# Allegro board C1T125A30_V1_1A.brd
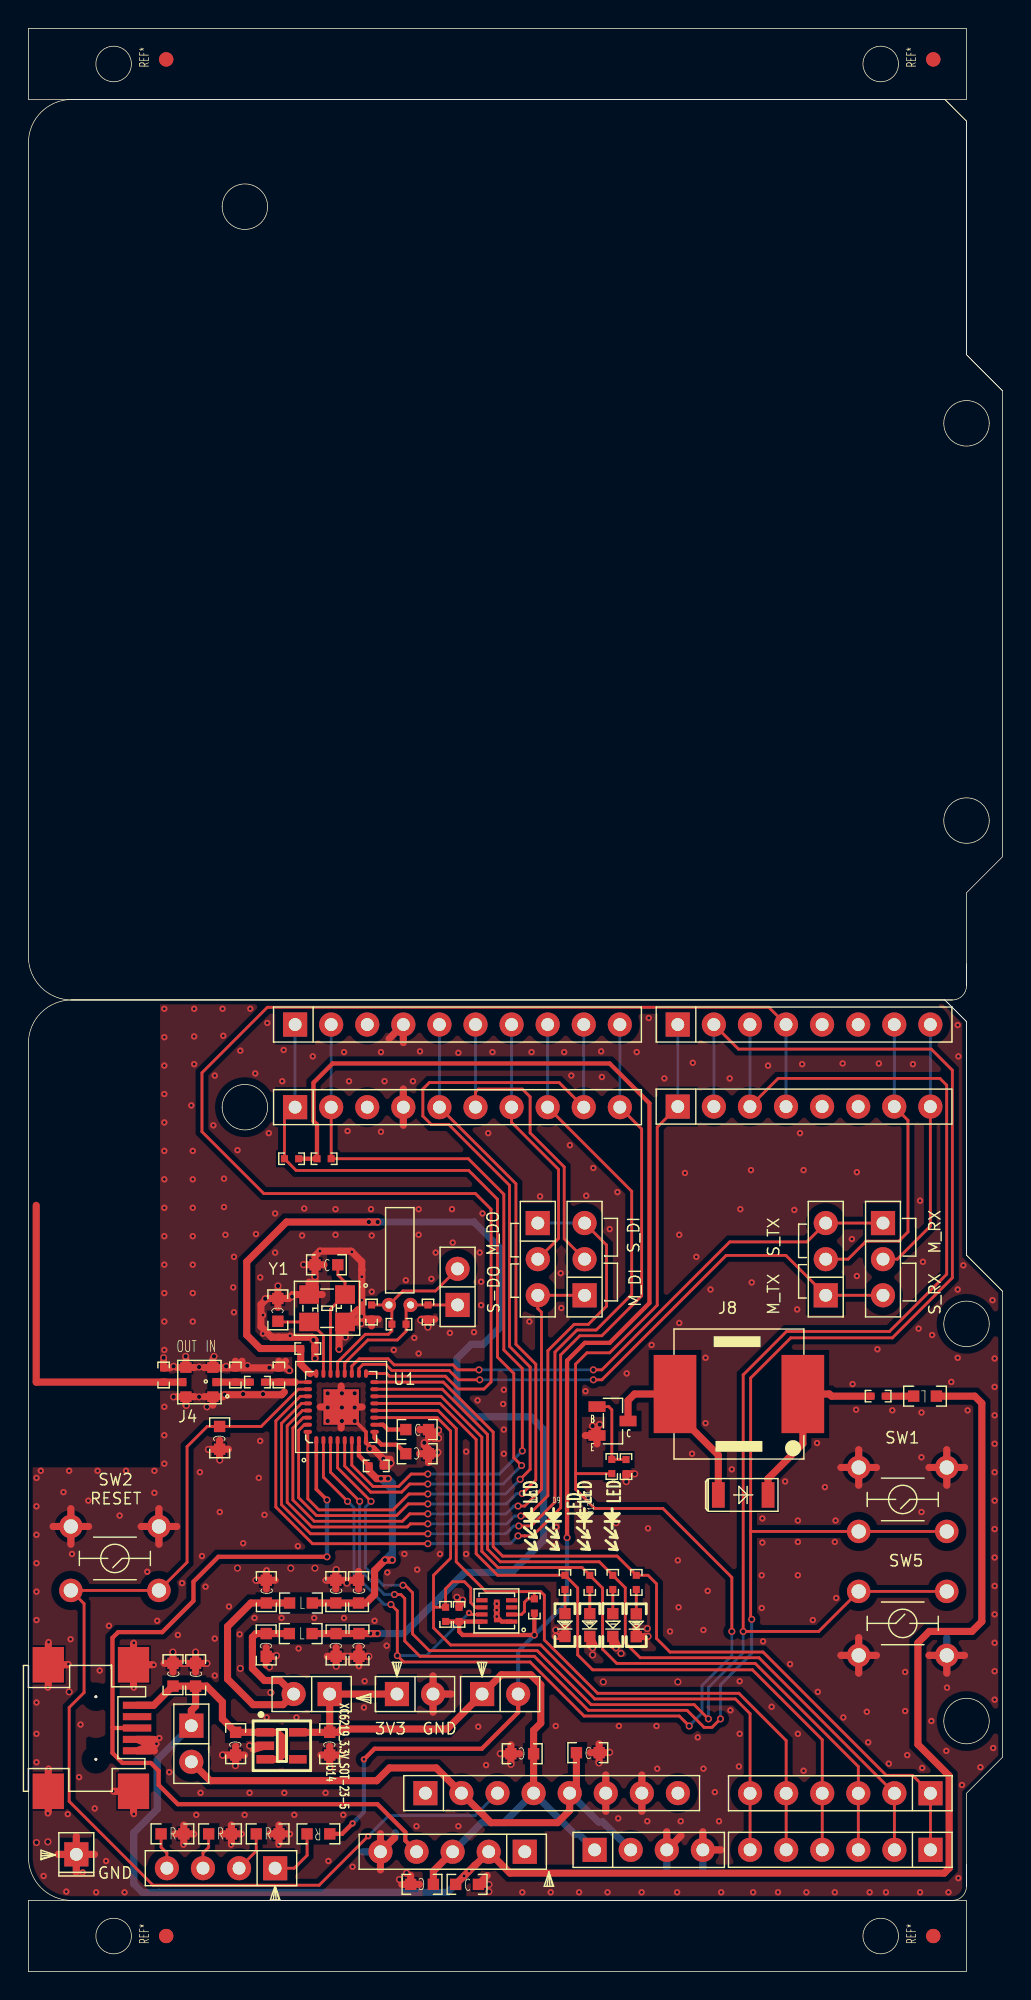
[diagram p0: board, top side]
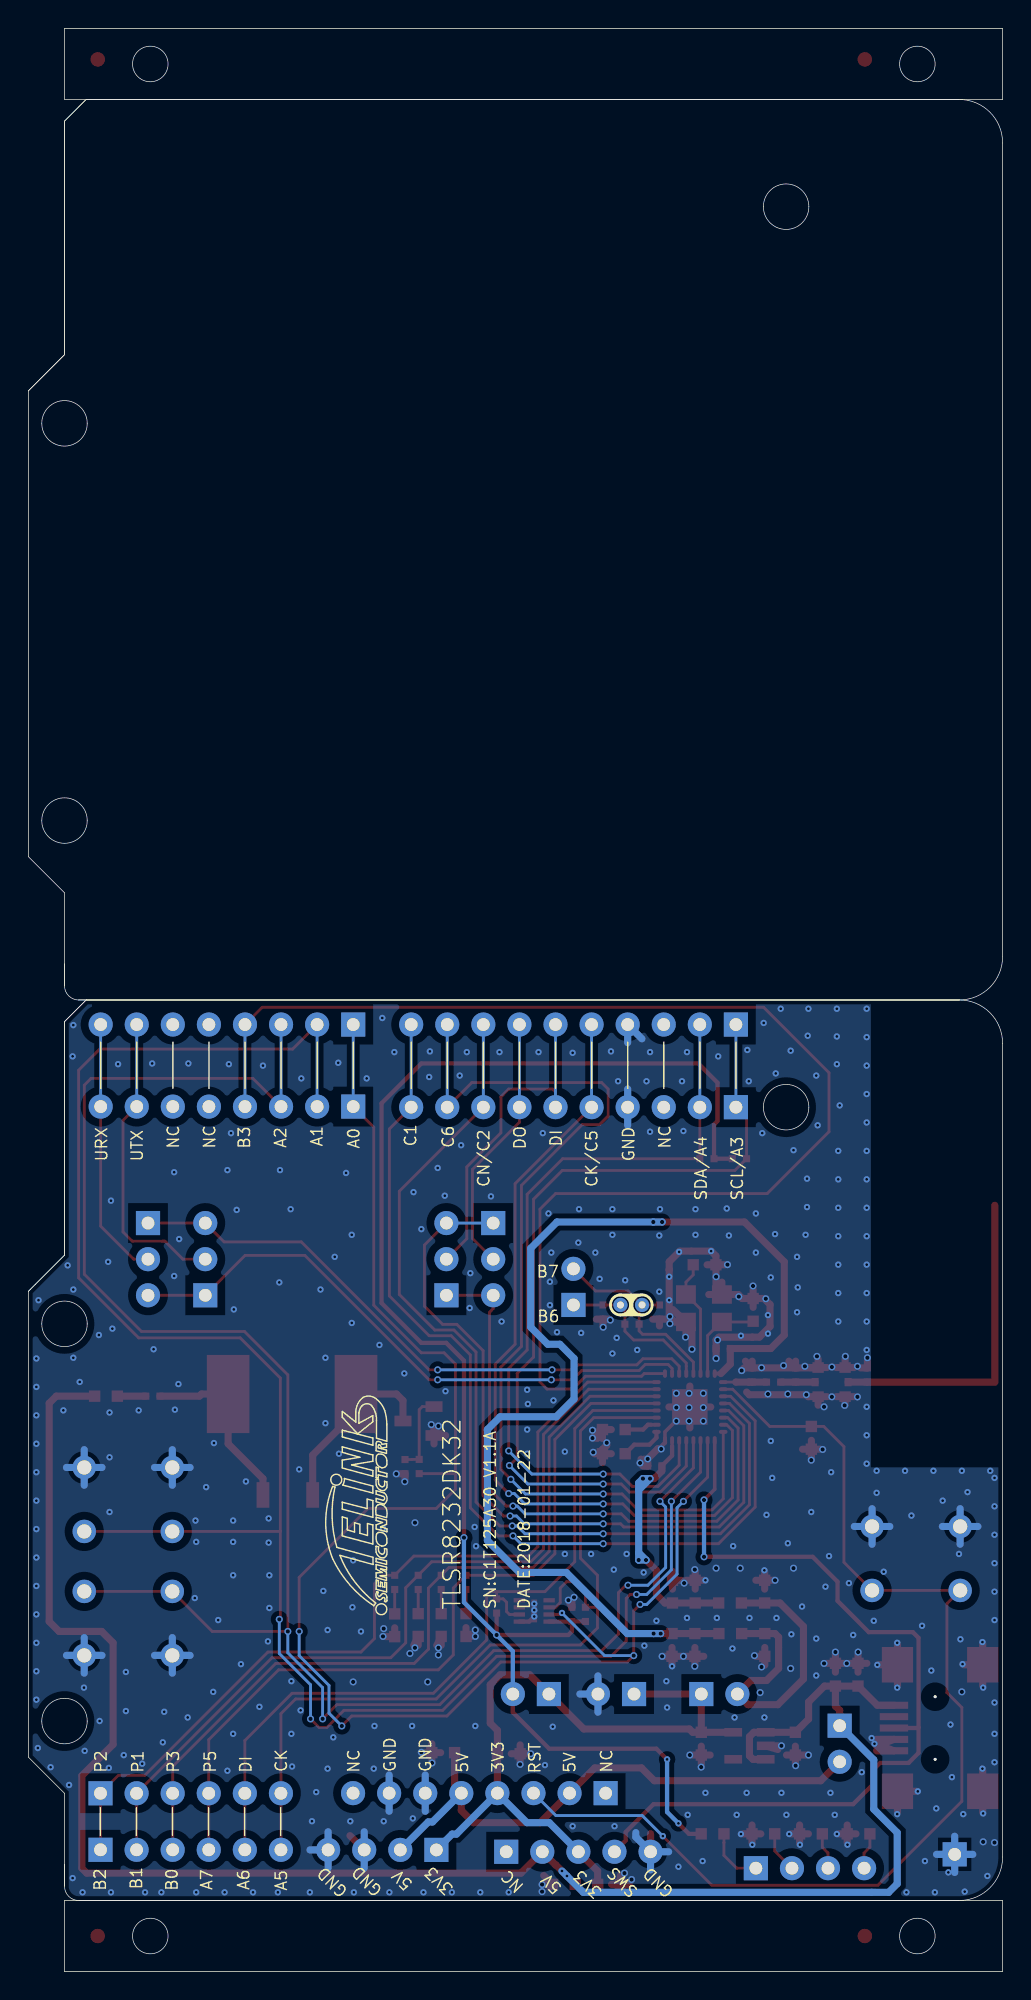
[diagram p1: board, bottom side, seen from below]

Outline 68.58 x 136.68 mm; copper layers: TOP, BOTTOM. Coordinates in mm from the lower left corner of the outline.
Outline path: circle c6,134.18 r1.25 ; circle c6,2.5 r1.25 ; circle c60,134.18 r1.25 ; circle c60,2.5 r1.25 ; 3.05,131.68 arc(0.89,130.79) 0,128.63 0,71.39 arc(0.89,69.23) 3.05,68.34 ; 3.05,131.68 64.52,131.68 ; 3.05,131.68 64.52,131.68 ; 3.05,68.34 arc(0.89,67.45) 0,65.29 0,8.05 arc(0.89,5.89) 3.05,5 ; 3.05,68.34 64.52,68.34 ; 3.05,68.34 65.04,68.34 ; 3.05,68.34 64.52,68.34 ; 3.05,68.34 65.04,68.34 ; 64.52,131.68 66.04,130.16 ; 64.52,131.68 66.04,130.16 ; 64.52,68.34 66.04,66.82 ; 64.52,68.34 66.04,66.82 ; 65.04,68.34 arc(65.75,68.63) 66.04,69.34 ; 3.05,5 65.04,5 ; 3.05,5 65.04,5 ; 65.04,5 arc(65.75,5.29) 66.04,6 ; 66.04,130.16 66.04,113.73 ; 66.04,130.16 66.04,113.73 ; 66.04,66.82 66.04,50.39 ; 66.04,66.82 66.04,50.39 ; 66.04,113.73 68.58,111.19 ; 66.04,113.73 68.58,111.19 ; 68.58,111.19 68.58,78.42 66.04,75.88 66.04,70.88 ; 66.04,70.88 66.04,69.34 ; 66.04,70.88 66.04,69.34 ; 66.04,50.39 68.58,47.85 ; 66.04,50.39 68.58,47.85 ; 68.58,47.85 68.58,15.08 66.04,12.54 66.04,7.54 ; 66.04,7.54 66.04,6 ; 66.04,7.54 66.04,6 ; 0,136.68 0,131.68 66.04,131.68 66.04,136.68 0,136.68 ; 0,5 66.04,5 66.04,0 0,0 0,5 ; 13.64,124.14 arc(15.24,125.74) 16.84,124.14 arc(15.24,122.54) 13.64,124.14 ; 13.64,60.8 arc(15.24,62.4) 16.84,60.8 arc(15.24,59.2) 13.64,60.8 ; 64.44,108.9 arc(66.04,110.5) 67.64,108.9 arc(66.04,107.3) 64.44,108.9 ; 64.44,80.96 arc(66.04,82.56) 67.64,80.96 arc(66.04,79.36) 64.44,80.96 ; 64.44,45.56 arc(66.04,47.16) 67.64,45.56 arc(66.04,43.96) 64.44,45.56 ; 64.44,17.62 arc(66.04,19.22) 67.64,17.62 arc(66.04,16.02) 64.44,17.62

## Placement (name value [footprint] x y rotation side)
C3  1uF  [0603C1]  13.46 37.54 270 top
C6  1uF  [0603C1]  27.37 36.42 180 top
C7  NC/1uF  [0402]  30.32 25.12 90 top
C9  1uF  [0603C1]  27.37 38.12 0 top
C10  NC  [0603C1]  20.98 49.72 0 top
C11  10uF  [0603C1]  34.76 15.32 180 top
C12  10uF  [0603C1]  39.38 15.4 0 top
C13  NC  [0603C1]  17.56 46.54 270 top
C14  1uF  [0603C1]  14.59 16.03 270 top
C15  NC  [0402]  24.16 46.39 90 top
C16  NC  [0402]  28.13 46.39 90 top
C17  1uF  [0603C1]  21.21 16.03 270 top
C18  1uF  [0603C1]  11.77 20.88 90 top
C19  10uF  [0603C1]  10.18 20.88 90 top
C20  1uF  [0603C1]  16.75 26.72 90 top
C21  0.1uF  [0603C1]  21.64 26.72 90 top
C22  1uF  [0603C1]  23.24 26.72 90 top
C23  0.1uF  [0402]  24.48 35.57 0 top
C24  1uF  [0603C1]  16.74 22.97 270 top
C25  0.1uF  [0603C1]  21.66 22.97 270 top
C26  1uF  [0603C1]  23.27 22.97 270 top
C27  0.1uF  [0402]  19.67 43.82 0 top
C33  1.8pF  [0402]  14.57 41.96 90 top
C34  1.8pF  [0402]  17.63 41.96 90 top
C39  NC/10uF  [0603C1]  27.71 6.13 180 top
C43  NC/10uF  [0603C1]  30.88 6.13 0 top
D1  Blue  [0603-LED]  39.52 24.37 270 top
D2  Green  [0603-LED]  37.77 24.37 270 top
D3  White  [0603-LED]  41.14 24.37 270 top
D4  Red  [0603-LED]  42.79 24.36 270 top
D7  NC/1N4148  [SOD80]  50.32 33.52 0 top
J3  HEADER 5  [HDR254F-1X5X850]  24.78 8.43 0 top
J4  MM8130  [MM8130-2600]  12.04 41.46 270 top
J5  VCC  [HDR254F-1X2X850]  11.47 14.75 90 top
J8  NC/Buzzer  [BUZZER]  50.02 40.62 180 top
J10  HEADER 1X2  [HDR254F-1X2X850]  30.21 49.43 270 top
J12  B2S  [HDR254F-1X2X850]  18.67 19.52 0 top
J13  NC  [HDR254F-1X2X850]  34.48 19.52 180 top
J15  USB_MiniABF  [USB-MINI-F5]  7.65 17.13 270 top
J18  Header_Femal  [HDR254F-1X6X850]  50.8 12.54 0 top
J19  Header_Femal  [HDR254F-1X8X850]  45.72 12.55 180 top
J20  Header_Femal  [HDR254F-1X10X850]  41.63 60.8 180 top
J21  Header_Mal  [HDR254F-1X6X850]  50.8 8.56 0 top
J22  Header_Femal  [HDR254F-1X8X850]  63.49 60.84 180 top
J29  Header_Mal  [HDR254F-1X10X850]  41.63 66.61 180 top
J31  Header_Mal  [HDR254F-1X8X850]  63.49 66.61 180 top
J32  Header_Mal  [HDR254F-1X4X850]  47.48 8.56 180 top
J33  UTX Jumper  [HDR254F-1X3X850]  56.13 52.65 270 top
J34  URX Jumper  [HDR254F-1X3X850]  60.16 47.57 90 top
J35  SPI_DO Jumper  [HDR254F-1X3X850]  35.86 47.57 90 top
J36  SPI_DI Jumper  [HDR254F-1X3X850]  39.15 52.65 270 top
J37  HEADER 4  [HDR254F-1X4X850]  9.75 7.27 0 top
J38  NC  [HDR254F-1X2X850]  28.48 19.52 180 top
J39  NC  [HDR254F-1X1X850]  3.37 8.24 90 top
L1  1.5nH  [0402]  9.52 41.96 90 top
L2  BEAD_600  [0603L1]  19.17 23.77 0 top
L3  BEAD_600  [0603L1]  19.19 25.92 0 top
L7  2.2nH  [0402]  16.12 41.46 180 top
L8  BEAD_600  [0603L1]  63.12 40.47 180 top
Q3  NC/8050  [BJT_SOT-23]  41.12 38.72 270 top
R1  NC  [0402]  26.09 45.54 180 top
R4  3.3K  [0402]  39.52 27.37 270 top
R5  750R  [0402]  37.77 27.37 270 top
R6  750R  [0402]  41.14 27.37 270 top
R7  750R  [0402]  42.79 27.37 270 top
R10  NC/1K  [0402]  41.07 35.52 90 top
R11  NC/2R  [0402]  59.82 40.47 0 top
R14  NC/3.3K  [0402]  18.53 57.17 180 top
R15  NC/3.3K  [0402]  20.81 57.17 0 top
R16  NC/2.2K  [0402]  35.62 25.72 90 top
R17  NC/2.2K  [0402]  29.37 25.12 90 top
R25  NC/1M  [0402]  42.07 35.52 270 top
R42  10K  [0603R]  16.84 9.69 0 top
R43  100K  [0603R]  20.42 9.69 180 top
R44  1M  [0603R]  13.49 9.69 0 top
R45  50K  [0603R]  10.14 9.69 0 top
REF*  value*  [unnamed]  9.7 134.5 90 top
REF*#2  value*  [unnamed]  63.7 2.5 90 top
REF*#3  value*  [unnamed]  9.7 2.5 90 top
REF*#4  value*  [unnamed]  63.7 134.5 90 top
SW1  SW4PIN_4.5x4.5  [BUTDIP4P_5P0X3P0]  61.55 33.21 180 top
SW2  SW4PIN_4.5x4.5  [BUTDIP4P_5P0X3P0]  6.09 29.06 180 top
SW5  SW4PIN_4.5x4.5  [BUTDIP4P_5P0X3P0]  61.55 24.49 0 top
U1  TLSR8232F512ET32  [QFN_5X5_32PIN_0P5_2P50X2P50]  22.02 39.71 90 top
U4  CE1132-33M  [SOT-23-5]  17.82 15.88 270 top
U5  NC/MFI  [CP]  32.97 25.37 90 top
Y1  24Mhz  [OSCCC250X320X110]  21.03 46.66 270 top
Y2  NC/32.768Khz-9pf-+/-20ppm  [OSC_2X6]  26.14 50.89 270 top

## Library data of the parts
C3 C6 C9 C14 C17 C18 C22 C26 = C1608X5R1C105M
C7 = C1005X5R1C105K
C10 C13 C15 C16 = C1608_NC
C11 C12 C19 C20 C24 C39 C43 = C1608X5R0J106M
C21 C25 = C1608X5R1H104M
C23 C27 = C1608X5R1H103K
C33 C34 = C1005_NC
D1-D4 = 0603D_Green
D7 = Diode_1N4148
J3 = HEADER 5: User Part Number: pn; Tolerance: RichardLC
J4 = MM8130
J5 J10 = B2S_3: User Part Number: pn; Tolerance: RichardLC
J8 = CONN MOD 8-2_J_0
J12 J13 = B2S_0: User Part Number: pn; Tolerance: RichardLC
J15 = USB_MiniABF_5pin: User Part Number: pn; Tolerance: RichardLC
J18 J21 = HEADER 6: User Part Number: pn; Tolerance: RichardLC
J19 J22 J31 = HEADER 8: User Part Number: pn; Tolerance: RichardLC
J20 J29 = HEADER 10: User Part Number: pn; Tolerance: RichardLC
J32 J37 = HEADER 4: User Part Number: pn; Tolerance: RichardLC
J33-J36 = HEADER 3: User Part Number: pn; Tolerance: RichardLC
J38 = HEADER 2: User Part Number: pn; Tolerance: RichardLC
J39 = HEADER 1: User Part Number: pn; Tolerance: RichardLC
L1 = MLK1005_000R
L2 L3 = MMZ1608Y601C
L7 = MLK1005S2N2ST
L8 = MMZ1005Y601C
Q3 = NPN_C1815
R1 = RS0402_NC
R4-R7 R10 R11 R25 = RS0402K102JT
R14 R15 = RS0402K332JT
R16 R17 = RS0402K222JT
R42-R45 = RS0603K104JT
SW1 SW2 SW5 = SW4PIN_0.5
U1 = TLSR8232F512ET32
U4 = XC6219_0.3V_SOT-23-5
U5 = XC6219_3.3V_SOT-23-5: User Part Number: pn; Tolerance: RichardLC
Y1 = CRYSTAL4/SM_0: Tolerance: RichardLC
Y2 = OSC_2x6_2pin

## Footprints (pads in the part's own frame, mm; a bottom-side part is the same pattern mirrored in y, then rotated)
0402
  rect 0.5x0.5 smd: 1(-0.5,0) 2(0.5,0)
0603-LED
  rect 0.8x0.8 smd: A(-0.8,0) C(0.8,0)
0603C1
  rect 0.8x0.8 smd: 1(-0.8,0) 2(0.8,0)
0603L1
  rect 0.8x0.8 smd: 1(-0.8,0) 2(0.8,0)
0603R
  rect 0.8x0.8 smd: 1(-0.8,0) 2(0.8,0)
BJT_SOT-23
  rect 0.75x1.2 smd: 1(-1.016,-1.092) 2(1.016,-1.092) 3(0,1.092)
BUTDIP4P_5P0X3P0
  round 1.65 hole 1: 1(-3.1,2.25) 2(-3.1,-2.25) 3(3.1,2.25) 4(3.1,-2.25)
BUZZER
  rect 3x5.5 smd: 1(-4.5,0) 2(4.5,0)
CP
  rect 0.3x0.8 smd: 1(-0.75,-1.05) 2(-0.25,-1.05) 3(0.25,-1.05) 4(0.75,-1.05) 5(0.75,1.05) 6(0.25,1.05) 7(-0.25,1.05) 8(-0.75,1.05)
  rect 1.6x0.4 smd: 9(0,0)
HDR254F-1X1X850
  rect 1.7x1.7 hole 0.9: 1(0,0)
HDR254F-1X2X850
  rect 1.7x1.7 hole 0.9: 1(2.54,0)
  round 1.7 hole 0.9: 2(0,0)
HDR254F-1X3X850
  rect 1.7x1.7 hole 0.9: 1(5.08,0)
  round 1.7 hole 0.9: 2(2.54,0) 3(0,0)
HDR254F-1X4X850
  rect 1.7x1.7 hole 0.9: 1(7.62,0)
  round 1.7 hole 0.9: 2(5.08,0) 3(2.54,0) 4(0,0)
HDR254F-1X5X850
  rect 1.7x1.7 hole 0.9: 1(10.16,0)
  round 1.7 hole 0.9: 2(7.62,0) 3(5.08,0) 4(2.54,0) 5(0,0)
HDR254F-1X6X850
  rect 1.7x1.7 hole 0.9: 1(12.7,0)
  round 1.7 hole 0.9: 2(10.16,0) 3(7.62,0) 4(5.08,0) 5(2.54,0) 6(0,0)
HDR254F-1X8X850
  rect 1.7x1.7 hole 0.9: 1(17.78,0)
  round 1.7 hole 0.9: 2(15.24,0) 3(12.7,0) 4(10.16,0) 5(7.62,0) 6(5.08,0) 7(2.54,0) 8(0,0)
HDR254F-1X10X850
  rect 1.7x1.7 hole 0.9: 1(22.86,0)
  round 1.7 hole 0.9: 2(20.32,0) 3(17.78,0) 4(15.24,0) 5(12.7,0) 6(10.16,0) 7(7.62,0) 8(5.08,0) 9(2.54,0) 10(0,0)
MM8130-2600
  rect 0.58x0.5 smd: 1(0,1.16) 2(0,-1.16)
  rect 0.75x0.8 smd: 3(-1.025,0.95) 4(1.025,0.95) 5(-1.025,-0.95) 6(1.025,-0.95)
OSC_2X6
  round 1 hole 0.5: 1(4,0.76) 2(4,-0.76)
OSCCC250X320X110
  rect 1.3x1.4 smd: 1(-0.965,1.265) 2(-0.965,-1.265) 3(0.965,-1.265) 4(0.965,1.265)
QFN_5X5_32PIN_0P5_2P50X2P50
  oval 0.6x0.28 smd: 1(-2.35,1.75) 2(-2.35,1.25) 3(-2.35,0.75) 4(-2.35,0.25) 5(-2.35,-0.25) 6(-2.35,-0.75) 7(-2.35,-1.25) 8(-2.35,-1.75) 17(2.35,-1.75) 18(2.35,-1.25) 19(2.35,-0.75) 20(2.35,-0.25) 21(2.35,0.25) 22(2.35,0.75) 23(2.35,1.25) 24(2.35,1.75)
  oval 0.28x0.6 smd: 9(-1.75,-2.35) 10(-1.25,-2.35) 11(-0.75,-2.35) 12(-0.25,-2.35) 13(0.25,-2.35) 14(0.75,-2.35) 15(1.25,-2.35) 16(1.75,-2.35) 25(1.75,2.35) 26(1.25,2.35) 27(0.75,2.35) 28(0.25,2.35) 29(-0.25,2.35) 30(-0.75,2.35) 31(-1.25,2.35) 32(-1.75,2.35)
  rect 2.5x2.5 smd: 33(0,0)
SOD80
  rect 0.9x1.8 smd: A(-1.75,0) C(1.75,0)
SOT-23-5
  rect 0.6x1.25 smd: 1(-0.95,-1.145) 2(0,-1.145) 3(0.95,-1.145) 4(0.95,1.145) 5(-0.95,1.145)
unnamed
  round 1 smd: 1(0,0) 2(0,0)
USB-MINI-F5
  round 0.2 hole 0.9 unplated: (-2.2,-2.9) (2.2,-2.9)
  rect 0.5x2 smd: 1(-1.6,0) 2(-0.8,0) 3(0,0) 4(0.8,0) 5(1.6,0)
  rect 2.5x2.2 smd: 6(-4.45,-6.25) 7(4.45,-6.25) 8(-4.45,-0.25) 9(4.45,-0.25)

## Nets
3V3: C11.1 C17.1 C39.1 J3.3 J12.1 J13.1 J19.4 J32.1 J38.1 U4.5(VOUT)
5V: C12.1 J5.2 J19.2 J19.5 J32.2
DVDD_IO: C7.1 J13.2 R14.1 R15.1 R16.1 R17.1 R43.1 U5.8(VCC)
GND: C3.2 C6.1 C7.2 C9.2 C10.1 C11.2 C12.2 C13.1 C14.2 C15.1 C16.1 C17.2 C18.2 C19.2 C20.2 C21.2 C22.2 C23.2 C24.2 C25.2 C26.2 C27.2 C33.2 C34.2 C39.2 C43.2 D1.C(CATHODE) D2.C(CATHODE) D3.C(CATHODE) D4.C(CATHODE) J3.5 J4.3 J4.4 J4.5 J4.6 J15.4(ID) J15.5(GND) J15.6(S1) J15.7(S2) J15.8(S3) J15.9(S4) J19.6 J19.7 J20.4 J29.4 J32.3 J32.4 J38.2 J39.1 L1.2 Q3.2(E) R25.2 R42.2 R44.2 R45.2 SW1.2 SW1.4 SW2.2 SW2.4 SW5.2 SW5.4 U1.8(DVSS) U1.33(GND) U4.2(VSS) U5.1(GND#1) U5.9(GND#9) Y1.2 Y1.4
VBUS: C14.1 C18.1 C19.1 C43.1 J3.2 J5.1 J15.1(V_BUS) L8.1 U4.1(VIN) U4.3(CE)
BUZ_5V: L8.2 R11.2
DI: J20.6 J29.6 J36.2
DO: J20.7 J29.7 J35.2
TL_A0: J22.1 J31.1 R10.1 U1.2(P0/P3/A[0]) U5.7(RST)
TL_A1: J22.2 J31.2 SW1.1 SW1.3 U1.3(P3N/UCTS/A[1])
TL_A2: J22.3 J31.3 SW5.1 SW5.3 U1.4(P1N/URTS/A[2])
TL_ANT: C34.1 L7.1 U1.25(ANT)
TL_AVDD: C20.1 C24.1 J12.2 L2.1 L3.1
TL_AVDD3_PIN24: C25.1 C26.1 C27.1 L2.2 U1.24(AVDD3)
TL_B3: J22.4 J31.4 U1.17(P0/MCK/URTS/I2CMSD/B[3])
TL_B6: C16.2 J10.1 R1.1 U1.20(P0N/I2C_MCK/URTS/B[6]) Y2.1
TL_B7: C15.2 J10.2 R1.2 U1.21(P1/I2C_MSD/UCTS/B[7]) Y2.2
TL_C1: J20.10 J29.10 U1.27(P2N/C[1])
TL_C6: J20.9 J29.9 U1.32(P4/C[6])
TL_CK/A5: J18.6 J21.6 R17.2 U1.11(P5/I2C_CK_MCK/A[5]) U5.6(SCL)
TL_CK/C5: J20.5 J29.5 U1.31(CK/I2C_MCK/MCK/URX/C[5])
TL_CN/C2: J20.8 J29.8 U1.28(CN/P0N/MCN/UCTS/C[2])
TL_DI/A6: J18.5 J21.5 R16.2 U1.12(P4N/I2C_SD_MSD/A[6]) U5.2(SDA)
TL_DI/C4: J35.3 J36.1 U1.30(DI/I2C_MSD/MDI/UTX/C[4])
TL_DO/C3: J35.1 J36.3 U1.29(DO/P5N/MDO/URTS/C[3])
TL_DVDD3: C21.1 C22.1 C23.1 L3.2 U1.7(DVDD3)
TL_DVDD3F: C9.1 U1.10(DVDD3_F)
TL_I2CCK/A3: J20.1 J29.1 R14.2 U1.5(P4/UTX/I2C_MCK/DI/A[3])
TL_I2CDI/A4: J20.2 J29.2 R15.2 U1.6(P2/URX/I2C_MSD/CK/A[4])
TL_P1/B1: J18.2 J21.2 R6.1 U1.15(P1/MDO/B[1])
TL_P2/B2: J18.1 J21.1 R7.1 U1.16(P2/MDI/UCTS/I2CMCK/B[2])
TL_P3/B0: J18.3 J21.3 R4.1 U1.14(P3/MCN/B[0])
TL_P5/A7: J18.4 J21.4 R5.1 U1.13(P5/A[7])
TL_RST: C3.1 J19.3 SW2.1 SW2.3 U1.26(RESETB)
TL_SWS: J3.4 J15.3(D+) U1.1(SWS/P3/C[7])
TL_URX/B5: J33.3 J34.1 U1.19(P4/URX/B[5])
TL_UTX/B4: J33.1 J34.3 U1.18(P1N/UTX/B[4])
TL_XC1: C13.2 U1.23(XC1) Y1.3
TL_XC2: C10.2 U1.22(XC2) Y1.1
URX: J22.8 J31.8 J34.2
UTX: J22.7 J31.7 J33.2
N19433324: Q3.1(B) R10.2 R25.1
N19433336: D7.A J8.2 Q3.3(C)
N19433338: D7.C J8.1 R11.1
N19452982: C6.2 U1.9(VDDDEC)
N19453491: C33.1 J4.1 L7.2
N19453517: J4.2 L1.1
N19478691: J37.2 R42.1
N19478703: J37.3 R44.1
N19478721: J37.4 R45.1
N19478794: J37.1 R43.2
N194550181: D4.A(ANODE) R7.2
N194550261: D2.A(ANODE) R5.2
N194550340: D1.A(ANODE) R4.2
N194550500: D3.A(ANODE) R6.2

Pads without a net: J3 1; J15 2; J19 1 8; J20 3; J22 5 6; J29 3; J31 5 6; REF* 1 2; REF*#2 1 2; REF*#3 1 2; REF*#4 1 2; U4 4; U5 3 4 5

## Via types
v1: diameter 0.5, hole 0.3, TOP to BOTTOM, 142 vias
v2: diameter 0.45, hole 0.2, TOP to BOTTOM, 358 vias

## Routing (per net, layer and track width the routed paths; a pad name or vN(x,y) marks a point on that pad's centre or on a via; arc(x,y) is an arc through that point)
3V3: length 50.5
  TOP w0.5: C17.1 21.82,16.83 22.05,17.06 29.48,17.06 J13.1 33.29,20.87 35.37,20.87 36.07,20.17 36.07,17.47 35.56,16.97 C11.1 J19.4 ; C17.1 U4.5 ; C17.1 J12.1 J38.1 ; C39.1 28.51,7.07 J3.3
  BOTTOM w0.5: J3.3 31.91,10.47 33.49,10.47 J19.4 38.45,9.67 38.75,9.67 J32.1
5V: length 39.7
  TOP w0.5: J5.2 12.8,13.42 24.52,13.42 25.42,14.32 28.71,14.32 J19.2 32.56,10.47 37.25,10.47 38.1,11.33 J19.5 38.58,13.03 C12.1
  BOTTOM w0.5: J19.5 40.13,10.52 40.43,10.52 J32.2
DVDD_IO: length 109
  TOP w0.3: U5.8 30.33,24.62 C7.1 ; v2(22.82,10.42) 22.08,9.69 R43.1 ; C7.1 30.32,23.92 30.57,23.67 v1(35.62,23.67) R16.1 ; C7.1 R17.1 ; R14.1 R15.1 20.31,59.58 20.07,59.82 20.07,62.52 21.42,63.87 40.92,63.87 43.72,61.07 43.72,47.02 40.92,44.22 39.17,44.22 37.92,42.97 v1(37.92,30.52) ; v2(23.62,14.92) 24.37,15.67 31.92,15.67 34.48,18.23 J13.2
  BOTTOM w0.3: J13.2 34.48,22.53 v1(35.62,23.67) 37.92,25.97 v1(37.92,30.52) ; v2(23.62,14.92) 23.62,11.22 v2(22.82,10.42)
GND: length 265.1
  TOP w0.25: U1.33 23.77,37.96 U1.8
  TOP w0.3: U5.1 33.33,24.62 32.97,24.97 U5.9 ; 24.19,36.77 23.77,37.2 U1.8
  TOP w0.5: J15.8 7.4,23.05 ; J15.8 8.72,21.58 ; J15.8 7.4,20.11 ; C13.1 17.56,47.96 ; C13.1 18.33,47.34 18.61,47.62 Y1.2 ; C13.1 17.56,46.72 ; C13.1 16.79,47.34 16.37,46.92 16.37,45.37 17.12,44.62 17.62,44.62 ; 11.09,39.84 J4.6 ; J4.6 11.71,40.44 ; J4.6 10.46,40.44 ; U1.33 23.49,39.71 ; U1.33 22.02,38.24 ; U1.33 20.55,39.71 ; U1.33 22.02,41.18 ; C15.1 24.63,45.89 ; C15.1 23.68,45.89 ; C15.1 24.16,45.42 ; 32.3,6.75 C43.2 32.3,6.13 ; SW5.2 58.45,23.49 ; SW5.2 57.2,22.24 ; SW5.2 59.7,22.24 ; SW5.2 58.45,20.99 ; 9.99,42.46 L1.2 9.52,42.93 ; C17.2 21.83,15.23 ; C17.2 21.21,14.61 ; C17.2 20.59,15.23 ; C17.2 21.21,15.85 ; C12.2 40.8,15.4 ; C12.2 40.18,16.02 ; C12.2 40.18,14.78 ; C12.2 39.56,15.4 ; 28.13,45.42 C16.1 ; C16.1 27.66,45.89 ; C16.1 28.6,45.89 ; 41.14,22.95 D3.C 41.45,22.95 ; Y1.2 20.18,48.04 C10.1 ; Y1.2 19.76,48.49 ; Y1.2 20.68,47.62 ; C34.2 18.1,42.93 ; C34.2 C33.2 ; C34.2 18.18,42.46 v1(18.37,42.27) ; C34.2 17.63,42.93 ; C23.2 25.22,36.04 ; C23.2 25.46,36.04 ; C23.2 v1(24.98,36.06) 24.27,36.77 24.19,36.77 ; C23.2 25.32,35.57 v1(25.52,35.77) ; C10.1 20.8,49.72 ; C10.1 19.56,49.72 ; C10.1 20.18,50.34 v2(20.52,50.67) 22.72,50.67 v2(22.77,50.62) 23.47,49.92 23.47,49.37 ; C20.2 16.75,28.15 ; C20.2 16.13,27.52 ; C20.2 16.75,26.9 ; C20.2 17.37,27.52 ; v1(28.87,38.07) 28.67,37.87 C9.2 ; SW1.4 58.45,36.71 ; SW1.4 58.45,34.21 ; SW1.4 57.2,35.46 ; SW1.4 59.7,35.46 ; 30.32,26.1 C7.2 30.55,26.1 ; 43.42,23.56 D4.C 42.79,24.18 ; 17.62,44.62 19.97,44.62 20.17,44.42 C27.2 v1(20.17,43.12) ; 17.62,44.62 17.63,44.61 ; 8.87,15.86 J15.4 8.87,16.33 ; C33.2 13.01,42.46 J4.3 ; C33.2 14.57,42.93 ; C33.2 15.04,42.93 ; 1.4,20.11 J15.6 ; J15.6 2.72,21.58 ; J15.6 1.4,23.05 ; C21.2 22.26,27.52 ; C21.2 21.02,27.52 ; C21.2 21.64,28.15 ; C21.2 21.64,26.9 ; 11.15,21.68 C18.2 ; C18.2 12.39,21.68 ; C18.2 11.77,22.3 ; C18.2 11.77,21.06 ; C26.2 23.89,22.17 ; C26.2 23.27,22.8 ; C26.2 23.27,21.55 ; C26.2 22.65,22.17 ; 40.64,11.28 J19.6 40.64,13.83 ; 6.08,12.68 J15.9 7.4,11.21 ; 2.1,8.24 J39.1 ; J39.1 4.65,8.24 ; J39.1 3.37,6.97 ; J39.1 3.37,9.52 ; J3.5 24.78,9.7 ; J3.5 24.78,7.15 ; J3.5 25.77,9.41 ; C25.2 22.28,22.17 ; C25.2 21.66,22.8 ; C25.2 21.04,22.17 ; C25.2 21.66,21.55 ; 26.29,6.13 C39.2 ; C39.2 26.91,6.75 ; C39.2 27.53,6.13 ; R45.2 10.94,10.31 ; R45.2 11.56,9.69 ; R45.2 10.32,9.69 ; R45.2 10.94,9.06 ; C19.2 10.8,21.68 ; C19.2 10.18,21.06 ; C19.2 10.18,22.3 ; C19.2 9.56,21.68 ; 37.77,24.19 D2.C 37.15,23.57 ; J38.2 29.76,19.52 ; J38.2 28.48,20.79 ; J38.2 28.48,18.25 ; J4.4 13.68,40.44 v1(13.82,40.57) 17.83,40.57 18.02,40.76 ; J4.4 12.36,40.44 ; J4.4 12.99,39.84 ; C6.1 28.17,36.72 27.87,37.02 v1(27.87,37.19) ; C6.1 28.17,35.8 ; C6.1 28.72,36.42 v1(28.82,36.52) ; C6.1 27.55,36.42 ; Y1.4 22.29,45.69 21.87,45.27 v1(21.87,43.77) ; Y1.4 23.21,46.56 ; Y1.4 22.29,44.82 ; Y1.4 23.07,45.69 23.47,46.09 v2(23.47,47.22) v2(23.47,48.87) 23.47,49.37 ; 26.39,59.53 J20.4 26.39,62.08 ; SW2.2 10.44,31.31 ; SW2.2 9.19,30.06 ; SW2.2 7.94,31.31 ; SW2.2 9.19,32.56 ; 28.17,37.5 C9.2 ; C9.2 28.52,37.52 v1(28.87,37.52) ; C9.2 27.55,38.12 ; J4.5 11.71,42.49 ; J4.5 10.46,42.49 ; J4.5 11.09,43.08 ; 17.64,9.06 R42.2 ; R42.2 18.26,9.69 ; R42.2 17.64,10.31 ; R42.2 17.02,9.69 ; 26.39,65.34 J29.4 25.39,65.61 ; 33.96,14.7 C11.2 ; C11.2 33.34,15.32 ; C11.2 33.96,15.94 ; C11.2 34.59,15.32 ; 39.83,22.95 D1.C 39.52,22.95 ; 13.46,36.12 C3.2 ; C3.2 12.84,36.74 ; C3.2 13.46,37.36 ; C3.2 14.08,36.74 ; R44.2 14.91,9.69 ; R44.2 13.67,9.69 ; R44.2 14.29,10.31 ; R44.2 14.29,9.06 ; 42.07,34.54 R25.2 42.54,35.02 ; 43.18,13.83 J19.7 43.18,11.28 ; 16.74,21.55 C24.2 ; C24.2 16.74,22.8 ; C24.2 17.36,22.17 ; 64.65,20.99 SW5.4 ; SW5.4 63.4,22.24 ; SW5.4 65.9,22.24 ; 23.47,49.37 23.48,49.36 ; 40.03,38.28 v1(40.22,38.47) ; 64.65,34.21 SW1.2 ; SW1.2 63.4,35.46 ; SW1.2 65.9,35.46 ; SW1.2 64.65,36.71 ; C14.2 14.59,15.85 ; C14.2 14.59,14.61 ; C14.2 15.21,15.23 ; C14.2 v1(13.67,15.23) ; 12.36,42.49 J4.3 ; J4.3 13.61,42.49 ; J4.3 12.99,43.08 ; 22.62,27.52 C22.2 ; C22.2 23.24,26.9 ; C22.2 23.24,28.15 ; 45.94,9.56 J32.3 44.94,9.83 ; 48.75,8.56 J32.4 47.48,9.83 ; 39.21,37.71 Q3.2 ; Q3.2 40.03,38.07 v1(39.72,38.37) ; Q3.2 40.03,37.11 ; SW2.4 4.24,31.31 ; SW2.4 2.99,30.06 ; SW2.4 2.99,32.56 ; SW2.4 1.74,31.31 ; 15.83,15.88 U4.2 15.83,15.62 ; 1.4,14.15 J15.7 1.4,11.21 ; 8.87,16 J15.5 8.87,15.53
  BOTTOM w0.5: SW2.4 4.24,31.31 ; SW2.4 2.99,32.56 ; SW2.4 2.99,30.06 ; SW2.4 1.74,31.31 ; 25.39,65.61 J29.4 26.39,65.34 ; 57.2,22.24 SW5.2 ; SW5.2 58.45,20.99 ; SW5.2 59.7,22.24 ; SW5.2 58.45,23.49 ; 24.78,7.15 J3.5 ; J3.5 25.82,9.46 25.82,9.77 ; J3.5 23.51,8.43 ; 57.2,35.46 SW1.4 ; SW1.4 59.7,35.46 ; SW1.4 58.45,34.21 ; SW1.4 58.45,36.71 ; 43.18,13.83 J19.7 43.18,11.28 ; 9.19,30.06 SW2.2 ; SW2.2 10.44,31.31 ; SW2.2 7.94,31.31 ; SW2.2 9.19,32.56 ; 26.39,59.53 J20.4 26.39,62.08 ; 44.94,9.83 J32.3 44.94,7.28 ; SW5.4 65.9,22.24 ; SW5.4 64.65,23.49 ; SW5.4 64.65,20.99 ; SW5.4 63.4,22.24 ; J38.2 29.76,19.52 ; J38.2 28.48,20.79 ; J38.2 28.48,18.25 ; J39.1 4.65,8.24 ; J39.1 3.37,6.97 ; J39.1 2.1,8.24 ; J39.1 3.37,9.52 ; 64.65,34.21 SW1.2 ; SW1.2 63.4,35.46 ; SW1.2 65.9,35.46 ; SW1.2 64.65,36.71 ; 47.48,7.28 J32.4 ; J32.4 47.48,9.83 ; J32.4 48.75,8.56 ; 40.64,13.83 J19.6 40.64,11.28
  vias: v1(0.57,9.07) v1(1.37,9.12) v1(2.87,19.67) v1(9.52,43.17) v1(10.22,42.57) v1(10.22,40.42) v1(10.17,22.47) v1(10.97,21.67) v1(11.07,43.27) v1(11.12,39.82) v1(11.77,22.47) v1(12.02,42.52) v1(12.02,40.42) v1(12.57,39.72) v1(12.57,21.67) v1(12.67,36.72) v1(13.07,43.27) v1(13.47,35.97) v1(13.92,42.57) v1(14.57,14.48) v1(14.72,28.37) v1(14.92,21.32) v1(15.12,40.62) v1(15.42,42.62) v1(15.57,15.88) v1(16.02,27.52) v1(16.52,40.62) v1(16.67,47.32) v1(16.97,42.47) v1(16.97,21.42) v1(17.07,19.62) v1(17.47,22.22) v1(17.57,48.22) v1(18.47,28.37) v1(18.57,47.47) v1(19.37,49.72) v1(20.07,44.42) v1(20.17,48.87) v1(20.17,28.37) v1(21.07,40.67) v1(21.07,39.67) v1(21.07,38.72) v1(21.22,14.38) v1(21.67,28.27) v1(21.67,21.47) v1(22.02,15.23) v1(22.07,40.67) v1(22.07,39.67) v1(22.07,38.72) v1(22.32,44.62) v1(22.42,27.32) v1(22.47,22.17) v1(22.97,40.67) v1(22.97,39.67) v1(22.97,38.72) v1(23.42,46.07) v1(23.42,45.57) v1(24.03,36.76) v1(23.97,22.17) v1(26.12,6.47) v1(26.62,6.92) v1(27.62,45.82) v1(28.12,45.32) v1(30.17,26.32) v1(30.57,26.12) v1(32.42,6.12) v1(32.42,5.62) v1(33.22,15.32) v1(33.97,14.57) v1(37.12,24.02) v1(37.12,23.57) v1(39.72,22.77) v1(39.72,22.27) v1(40.17,14.67) v1(40.47,20.37) v1(40.92,15.42) v1(41.37,31.57) v1(41.37,22.77) v1(41.72,22.37) v1(42.08,34.46) v1(42.68,35.01) v1(43.57,24.12) v1(43.62,23.57) v1(45.72,20.37) v2(0.57,34.72) v2(0.57,32.72) v2(0.57,30.72) v2(0.57,28.72) v2(0.57,26.72) v2(0.57,24.72) v2(0.57,18.92) v2(0.57,16.72) v2(0.57,14.72) v2(0.87,35.22) v2(1.07,6.72) v2(1.42,23.17) v2(1.37,19.97) v2(1.42,14.27) v2(1.37,11.12) v2(2.47,33.72) v2(2.67,5.62) v2(2.82,21.62) v2(2.77,11.07) v2(2.87,35.22) v2(2.97,23.37) v2(3.07,29.37) v2(3.57,13.67) v2(3.67,17.37) v2(3.82,6.97) v2(4.22,33.12) v2(4.67,11.47) v2(4.77,5.57) v2(4.87,35.22) v2(5.02,21.17) v2(5.47,7.77) v2(5.67,24.32) v2(5.97,12.67) v2(6.42,32.07) v2(6.77,5.57) v2(6.87,35.22) v2(7.42,23.12) v2(7.42,19.97) v2(7.42,11.07) v2(8.37,28.12) v2(8.82,21.57) v2(8.87,35.22) v2(8.87,33.67) v2(9.02,16.02) v2(9.07,24.67) v2(9.22,16.42) v2(9.57,67.72) v2(9.57,65.72) v2(9.57,63.72) v2(9.57,61.72) v2(9.57,59.72) v2(9.57,57.72) v2(9.57,55.72) v2(9.57,53.72) v2(9.57,51.72) v2(9.57,49.72) v2(9.57,47.72) v2(9.57,45.72) v2(9.57,43.72) v2(9.57,39.72) v2(9.57,37.72) v2(9.57,35.72) v2(9.92,14.02) v2(10.52,23.67) v2(10.82,27.32) v2(10.92,8.92) v2(11.47,60.92) v2(11.57,57.72) v2(11.57,55.72) v2(11.57,53.72) v2(11.57,51.72) v2(11.57,49.72) v2(11.57,47.72) v2(11.57,45.72) v2(11.67,67.72) v2(11.67,65.77) v2(11.67,63.82) v2(11.67,9.67) v2(11.82,11.02) v2(12.07,35.12) v2(12.12,12.57) v2(12.22,29.22) v2(12.47,27.07) v2(13.02,59.52) v2(13.12,63.02) v2(13.12,23.42) v2(13.12,20.82) v2(13.47,32.32) v2(13.67,67.72) v2(13.72,65.82) v2(13.77,55.77) v2(13.77,53.77) v2(13.87,51.82) v2(14.12,25.67) v2(14.27,8.92) v2(14.42,48.12) v2(14.47,50.27) v2(14.47,46.37) v2(14.72,57.77) v2(14.92,64.77) v2(14.87,23.72) v2(15.02,9.67) v2(15.12,30.12) v2(15.22,11.02) v2(15.62,67.72) v2(15.57,12.57) v2(15.92,24.87) v2(15.97,63.17) v2(16.02,51.87) v2(16.22,34.72) v2(16.32,48.82) v2(16.32,37.32) v2(16.52,46.17) v2(16.52,44.87) v2(16.62,32.12) v2(16.82,66.72) v2(16.77,28.22) v2(16.77,17.87) v2(16.92,58.97) v2(17.37,53.32) v2(17.37,50.57) v2(17.62,8.92) v2(17.82,24.87) v2(17.87,62.62) v2(17.97,64.82) v2(18.02,12.57) v2(18.42,44.72) v2(18.42,9.67) v2(18.72,11.02) v2(18.87,17.87) v2(18.97,29.92) v2(19.02,22.72) v2(19.27,51.77) v2(19.42,53.67) v2(20.02,64.37) v2(20.12,24.87) v2(20.92,27.52) v2(20.92,12.57) v2(21.12,7.77) v2(21.62,53.62) v2(21.62,51.82) v2(22.22,64.67) v2(22.22,24.87) v2(22.17,11.02) v2(22.47,59.12) v2(22.57,62.62) v2(22.82,7.37) v2(23.27,21.47) v2(23.62,18.57) v2(23.67,20.42) v2(24.12,53.62) v2(24.17,51.77) v2(24.17,47.82) v2(24.37,24.67) v2(24.82,64.67) v2(24.82,59.07) v2(25.07,62.62) v2(25.22,22.92) v2(25.27,28.07) v2(25.72,43.72) v2(26.47,29.37) v2(26.57,48.62) v2(27.07,62.62) v2(27.17,44.57) v2(27.32,10.22) v2(27.37,28.27) v2(27.47,53.62) v2(27.47,51.82) v2(27.47,43.47) v2(27.57,64.72) v2(28.37,48.72) v2(28.67,50.57) v2(28.97,29.37) v2(29.67,44.92) v2(29.82,53.62) v2(29.87,51.27) v2(30.27,64.62) v2(30.27,10.22) v2(30.82,36.57) v2(30.82,29.37) v2(31.37,44.97) v2(31.62,40.17) v2(31.67,17.22) v2(31.77,50.57) v2(31.87,48.52) v2(31.87,46.87) v2(31.97,53.32) v2(32.22,14.52) v2(32.37,58.97) v2(32.67,64.67) v2(32.97,25.87) v2(32.97,25.42) v2(32.97,24.97) v2(33.42,39.92) v2(33.47,40.92) v2(33.47,38.12) v2(33.47,36.42) v2(34.77,5.57) v2(35.27,45.72) v2(35.42,64.67) v2(36.02,54.52) v2(36.77,5.57) v2(37.07,29.92) v2(37.12,17.27) v2(37.17,31.27) v2(37.47,49.12) v2(37.52,46.67) v2(37.72,64.67) v2(38.12,58.12) v2(38.22,63.02) v2(38.77,5.57) v2(39.22,40.82) v2(39.27,54.57) v2(39.77,56.52) v2(40.32,64.72) v2(40.37,62.92) v2(40.77,5.57) v2(40.92,52.22) v2(41.47,54.82) v2(41.52,10.77) v2(41.57,17.27) v2(42.12,42.07) v2(42.82,64.67) v2(43.17,5.57) v2(43.62,31.17) v2(43.57,10.57) v2(43.67,67.07) v2(43.87,44.07) v2(44.22,17.27) v2(44.27,14.27) v2(44.77,62.82) v2(45.17,23.92) v2(45.72,28.92) v2(45.67,5.57) v2(45.82,51.82) v2(45.82,45.62) v2(45.77,25.62) v2(45.92,10.57) v2(46.22,56.17) v2(46.72,36.42) v2(46.77,63.92) v2(47.02,50.27) v2(47.12,16.47) v2(47.52,24.02) v2(47.52,14.27) v2(47.67,43.17) v2(47.67,38.57) v2(47.82,26.77) v2(48.02,47.97) v2(48.32,12.62) v2(48.62,10.57) v2(48.77,5.57) v2(49.37,62.82) v2(49.42,18.37) v2(49.52,35.32) v2(50.02,14.42) v2(50.12,53.62) v2(50.07,20.42) v2(50.07,16.72) v2(50.87,56.37) v2(50.92,48.47) v2(51.02,5.57) v2(51.62,27.87) v2(51.62,25.57) v2(51.67,31.87) v2(51.67,30.17) v2(51.72,23.22) v2(52.07,63.72) v2(52.32,18.62) v2(52.77,5.57) v2(53.27,34.47) v2(53.62,21.62) v2(53.92,53.57) v2(54.12,46.57) v2(54.17,31.72) v2(54.17,30.22) v2(54.17,27.87) v2(54.17,16.72) v2(54.32,58.97) v2(54.47,63.82) v2(54.57,56.37) v2(54.57,14.12) v2(54.77,5.57) v2(55.22,24.72) v2(55.52,37.17) v2(55.57,19.67) v2(56.07,34.07) v2(56.82,31.72) v2(56.77,30.22) v2(56.77,5.57) v2(56.87,26.27) v2(57.32,63.87) v2(57.37,17.87) v2(57.97,51.52) v2(58.02,41.32) v2(58.32,56.22) v2(58.32,48.92) v2(58.27,39.52) v2(59.02,18.27) v2(59.12,16.12) v2(59.22,5.57) v2(59.77,43.77) v2(59.87,63.87) v2(60.37,5.57) v2(60.57,14.62) v2(60.82,39.47) v2(61.72,21.07) v2(61.72,18.32) v2(61.87,15.22) v2(62.27,63.82) v2(62.67,45.22) v2(62.77,54.22) v2(62.77,5.57) v2(62.87,39.32) v2(62.87,36.17) v2(62.87,32.32) v2(62.92,14.32) v2(62.97,49.92) v2(63.62,44.77) v2(63.57,17.62) v2(64.62,15.52) v2(64.67,19.97) v2(64.77,5.57) v2(64.97,41.47) v2(65.42,66.57) v2(65.42,47.97) v2(65.42,43.17) v2(65.47,64.37) v2(65.47,6.57) v2(65.72,13.12) v2(65.82,49.67) v2(66.12,39.47) v2(67.02,14.37) v2(67.87,47.22) v2(67.92,15.72) v2(68.02,43.12) v2(68.02,41.12) v2(68.02,39.12) v2(68.02,37.12) v2(68.02,35.12) v2(68.02,33.12) v2(68.02,31.12) v2(68.02,29.12) v2(68.02,27.12) v2(68.02,25.12) v2(68.02,23.12) v2(68.02,21.12) v2(68.02,19.12)
VBUS: length 132.8
  TOP w0.5: C18.1 11.77,18.67 11.47,18.37 J5.1 ; C18.1 12.54,20.08 13.66,18.96 13.66,17.76 C14.1 U4.1 17.51,16.83 17.82,16.52 17.82,15.17 17.57,14.92 16.68,14.92 U4.3 ; C18.1 C19.1 10.17,20.08 8.82,18.73 J15.1 ; C43.1 30.08,6.13 v2(30.67,6.72) v2(31.02,7.07) 31.44,7.49 31.47,7.49 J3.2 33.91,6.92 64.47,6.92 64.82,7.27 64.82,13.77 62.62,15.97 62.62,23.12 63.42,23.92 66.42,23.92 67.12,24.62 67.12,39.97 66.62,40.47 L8.1
  BOTTOM w0.5: v2(31.02,7.07) v2(30.67,6.72) 29.52,5.57 9.22,5.57 8.02,5.57 7.42,6.17 7.42,9.77 9.07,11.42 9.07,14.89 J5.1
BUZ_5V: length 2
  TOP w0.5: L8.2 R11.2
DI: length 24
  TOP w0.2: J20.6 31.47,61.87 31.68,62.07 34.77,62.07 35.32,61.52 35.32,58.99 37.72,56.59 37.72,51.54 J36.2
  BOTTOM w0.2: J29.6 J20.6
DO: length 18.5
  TOP w0.2: J20.7 34.01,59.73 37.32,56.43 37.32,51.57 J35.2
  BOTTOM w0.2: J29.7 J20.7
TL_A0: length 111.8
  TOP w0.2: J22.1 44.27,59.4 44.27,46.87 40.92,43.52 39.32,43.52 38.52,42.72 38.52,35.02 ; v2(31.02,25.22) 31.13,25.12 U5.7 ; 38.52,35.02 38.52,33.92 39.87,32.57 44.67,32.57 49.52,27.72 v1(49.52,23.92) ; 38.52,35.02 R10.1 ; v1(25.52,25.82) 25.97,25.37 v1(25.97,22.22) 26.42,21.77 35.32,21.77 39.12,17.97 45.82,17.97 v1(46.52,17.27) ; U1.2 20.77,34.78 v1(22.47,33.07)
  BOTTOM w0.2: J31.1 J22.1 ; v1(22.47,33.07) 22.92,32.62 22.92,27.95 25.05,25.82 v1(25.52,25.82) ; v1(46.52,17.27) 47.42,18.17 47.42,20.12 49.52,22.22 v1(49.52,23.92) ; v2(31.02,25.22) 28.02,22.22 v1(25.97,22.22)
TL_A1: length 136.3
  TOP w0.2: SW1.1 SW1.3 50.86,30.96 50.84,30.97 ; 50.84,30.97 50.84,41.75 53.67,44.57 60.82,44.57 65.04,48.8 65.04,63.4 63.56,64.89 49.98,64.89 J31.2 ; 50.84,30.97 50.84,24.85 v1(50.92,24.77) ; v1(25.77,26.52) 26.22,26.52 26.49,26.25 26.49,23.25 27.57,22.17 35.62,22.17 39.42,18.37 46.37,18.37 47.57,17.17 48.12,17.17 v1(48.72,17.77) ; v1(23.32,33.07) 21.27,35.13 U1.3
  BOTTOM w0.2: v1(50.92,24.77) 50.92,22.37 48.72,20.17 v1(48.72,17.77) ; J31.2 J22.2 ; v1(23.32,33.07) 23.32,28.26 25.05,26.52 v1(25.77,26.52)
TL_A2: length 132.2
  TOP w0.2: v1(24.12,33.07) 21.77,35.43 U1.4 ; v1(47.87,17.77) 46.87,18.77 39.62,18.77 35.82,22.57 28.22,22.57 27.04,23.75 27.04,26.65 26.52,27.17 v1(26.37,27.17) ; SW5.3 SW5.1 55.63,23.92 v1(50.32,23.92) 50.32,41.97 53.37,45.02 60.62,45.02 64.64,49.05 64.64,62.35 64.17,62.82 52.78,62.82 J22.3
  BOTTOM w0.2: v1(26.37,27.17) 24.97,27.17 23.72,28.42 23.72,32.67 v1(24.12,33.07) ; v1(50.32,23.92) 50.32,22.42 47.87,19.97 v1(47.87,17.77) ; J31.3 J22.3
TL_ANT: length 3
  TOP w0.2: 18.77,41.46 U1.25
  TOP w0.5: L7.1 C34.1 17.88,41.46 17.88,41.46 18.77,41.46
TL_AVDD: length 23
  TOP w0.5: L2.1 C24.1 16.02,23.77 15.77,23.52 15.77,22.82 15.77,21.32 16.62,20.47 17.72,20.47 J12.2 17.92,18.77 15.82,18.77 14.02,20.57 14.02,24.27 15.67,25.92 C20.1 L3.1
TL_AVDD3_PIN24: length 78.9
  TOP w0.28: U1.24 19.83,42.06
  TOP w0.5: v1(24.59,52.72) v1(23.97,52.72) 18.17,52.72 15.37,49.92 15.37,44.77 16.32,43.82 C27.1 19.17,42.72 19.83,42.06 ; L2.2 C25.1 C26.1 v1(24.07,23.77) v1(24.57,23.77)
  BOTTOM w0.5: v1(24.07,23.77) v1(24.57,23.77) 26.42,23.77 30.72,28.07 34.02,28.07 36.27,30.32 36.27,38.12 35.37,39.02 31.42,39.02 30.17,40.27 30.17,43.12 31.17,44.12 32.02,44.12 33.22,45.32 33.22,50.87 31.37,52.72 v1(24.59,52.72) v1(23.97,52.72)
TL_B3: length 97.7
  TOP w0.2: J31.4 52.12,67.82 16.82,67.82 12.22,63.22 12.22,59.07 16.57,54.72 31.47,54.72 32.57,53.62 32.57,41.47 32.07,40.97 30.26,40.97 29.36,41.87 25.42,41.87 25.23,42.06 U1.17
  BOTTOM w0.2: J31.4 J22.4
TL_B6: length 11.3
  TOP w0.2: J10.1 C16.2 Y2.1 26.59,46.57 R1.1 26.59,45.04 25.97,44.42 23.89,44.42 22.27,42.8 22.27,42.58 22.27,42.58 U1.20
TL_B7: length 14.6
  TOP w0.2: Y2.2 26.37,47.87 28.66,47.87 J10.2 ; Y2.2 C15.2 ; Y2.2 25.59,46.68 R1.2 25.59,45.07 25.34,44.82 23.72,44.82 21.77,42.87 U1.21
TL_C1: length 69.1
  TOP w0.2: U1.27 19.15,40.46 17.42,38.73 17.42,32.67 20,30.09 v1(28.12,30.09) ; v1(34.47,30.65) 34.94,30.65 34.94,30.64 35.49,30.64 37.47,32.62 37.47,43.37 38.82,44.72 40.37,44.72 43.17,47.52 43.17,59.27 J20.10
  BOTTOM w0.2: v1(28.12,30.09) 33.92,30.09 v1(34.47,30.65) ; J29.10 J20.10
TL_C6: length 70.5
  TOP w0.2: J20.9 37.36,62.53 28.23,62.53 27.77,62.07 27.77,60.17 28.37,59.57 29.6,59.57 33.87,55.3 33.87,43.97 35.32,42.52 35.32,35.32 v1(34.62,34.62) ; U1.32 19.67,33.25 20.45,32.47 25.67,32.47 26.79,33.59 v1(28.12,33.59)
  BOTTOM w0.2: J29.9 J20.9 ; v1(34.62,34.62) 33.59,33.59 v1(28.12,33.59)
TL_CK/A5: length 60.7
  TOP w0.2: 28.52,25.67 28.52,27.87 29.72,29.07 29.72,38.02 28.78,38.96 U1.11 ; 28.52,25.67 28.52,24.17 29.72,22.97 36.07,22.97 39.87,19.17 49.77,19.17 50.8,18.14 J18.6 J21.6 ; 28.52,25.67 28.57,25.62 R17.2 29.37,26.92 29.87,27.42 30.69,27.42 31.14,26.97 31.14,25.95 31.48,25.62 U5.6
TL_CK/C5: length 58.6
  TOP w0.2: v1(34.77,33.62) 35.72,34.57 35.72,42.72 34.32,44.12 34.32,55.42 J20.5 ; v1(28.12,32.89) 26.74,32.89 25.92,32.07 20.28,32.07 19.02,33.34 19.02,38.06 19.42,38.46 U1.31
  BOTTOM w0.2: J29.5 J20.5 ; v1(34.77,33.62) 34.37,33.62 33.64,32.89 v1(28.12,32.89)
TL_CN/C2: length 68.2
  TOP w0.2: U1.28 19.22,39.96 17.82,38.56 17.82,32.84 19.86,30.79 v1(28.12,30.79) ; v1(34.52,31.34) 35.39,31.34 37.07,33.02 37.07,43.57 38.62,45.12 39.97,45.12 42.47,47.62 42.47,54.89 J20.8
  BOTTOM w0.2: v1(28.12,30.79) 33.62,30.79 34.17,31.34 v1(34.52,31.34) ; J29.8 J20.8
TL_DI/A6: length 56.6
  TOP w0.2: U5.2 34.71,25.12 34.92,25.32 34.92,25.97 35.16,26.22 R16.2 35.62,26.72 ; 35.62,26.72 36.07,26.72 36.32,26.47 36.32,23.32 40.07,19.57 50.02,19.57 53.34,16.25 J18.5 J21.5 ; 35.62,26.72 32.22,26.72 30.12,28.82 30.12,38.19 28.85,39.46 U1.12
TL_DI/C4: length 42.5
  TOP w0.2: U1.30 19.35,38.96 18.62,38.23 18.62,33.17 20.12,31.67 26.32,31.67 26.84,32.19 v1(28.12,32.19) ; v1(34.47,32.74) 34.94,32.74 36.12,33.92 36.12,46.37 35.86,46.63 J35.3 J36.1
  BOTTOM w0.2: v1(28.12,32.19) 33.62,32.19 34.17,32.74 v1(34.47,32.74)
TL_DO/C3: length 52.7
  TOP w0.2: J36.3 40.7,51.1 40.7,46.8 39.42,45.52 38.42,45.52 36.57,43.67 36.57,33.47 35.14,32.04 v1(34.67,32.04) ; U1.29 19.29,39.46 18.22,38.39 18.22,33.01 19.95,31.27 26.67,31.27 26.89,31.49 v1(28.12,31.49)
  BOTTOM w0.2: v1(28.12,31.49) 33.67,31.49 34.22,32.04 v1(34.67,32.04) ; J35.1 J36.3
TL_DVDD3: length 20.6
  TOP w0.2: U1.7 23.27,36.97
  TOP w0.3: 23.27,36.97 23.27,36.29 C23.1
  TOP w0.5: L3.2 C21.1 C22.1 23.77,25.92 24.37,26.52 24.37,28.21 v1(25.1,28.95) v1(25.62,28.95) ; v1(25.32,34.67) v1(24.82,34.67) 24.52,34.67 23.98,35.21 C23.1
  BOTTOM w0.5: 25.62,33.87 25.62,29.46 ; 25.62,33.87 v1(24.82,34.67) v1(25.32,34.67) 25.62,34.37 25.62,33.87 ; 25.62,29.46 v1(25.62,28.95) v1(25.1,28.95) 25.62,29.46
TL_DVDD3F: length 2.3
  TOP w0.2: 24.72,38.46 U1.10
  TOP w0.3: 24.72,38.46 24.97,38.46 25.31,38.12 C9.1
TL_I2CCK/A3: length 61.2
  TOP w0.2: v1(28.12,34.29) 26.84,34.29 26.27,33.72 24.1,33.72 22.27,35.55 U1.5 ; v1(34.72,35.59) 34.17,36.14 34.17,42.07 33.02,43.22 33.02,54.32 30.99,56.35 18.85,56.35 R14.2 18.03,60.05 J20.1
  BOTTOM w0.2: J29.1 J20.1 ; v1(34.72,35.59) 33.42,34.29 v1(28.12,34.29)
TL_I2CDI/A4: length 56.6
  TOP w0.2: v1(34.77,36.62) 34.77,42.42 33.47,43.72 33.47,54.67 30.97,57.17 R15.2 J20.2 ; v1(28.12,34.99) 26.94,34.99 26.07,34.12 24.26,34.12 22.77,35.62 U1.6
  BOTTOM w0.2: J29.2 J20.2 ; v1(28.12,34.99) 33.14,34.99 v1(34.77,36.62)
TL_P1/B1: length 59.3
  TOP w0.2: J21.2 J18.2 51.43,22.07 43.07,22.07 42.02,23.12 42.02,26.99 R6.1 40.19,28.82 33.22,28.82 32.32,29.72 32.32,37.78 29.14,40.96 U1.15
TL_P2/B2: length 62.1
  TOP w0.2: J21.1 J18.1 62.25,13.8 60.39,13.8 51.72,22.47 45.17,22.47 44.22,23.42 44.22,27.27 43.62,27.87 R7.1 41.44,29.22 33.38,29.22 32.72,29.89 32.72,37.95 29.2,41.46 U1.16
TL_P3/B0: length 57.9
  TOP w0.2: J21.3 J18.3 58.42,14.42 51.17,21.67 41.42,21.67 40.42,22.67 40.42,26.97 R4.1 38.97,28.42 33.05,28.42 31.92,29.56 31.92,37.59 29.05,40.46 U1.14
TL_P5/A7: length 56.5
  TOP w0.2: U1.13 28.98,39.96 31.52,37.42 31.52,29.39 33.03,27.87 R5.1 38.67,26.98 38.67,22.27 39.72,21.22 50.97,21.22 55.88,16.31 J18.4 J21.4
TL_RST: length 78.2
  TOP w0.2: v2(23.92,9.52) 20.47,6.07 8.77,6.07 2.87,11.97 2.87,18.57 3.92,19.62 3.92,25.88 SW2.3 SW2.1 11.17,28.79 11.17,36.92 12.59,38.34 C3.1 16.39,38.34 19.01,40.96 U1.26
  BOTTOM w0.2: v2(23.92,9.52) 25.37,10.97 31.45,10.97 J19.3
TL_SWS: length 61.8
  TOP w0.25: v1(21.02,33.17) 20.27,33.93 U1.1
  TOP w0.3: v1(21.02,29.17) 13.37,29.17 11.62,27.42 11.62,26.07 9.42,23.87 6.32,23.87 5.92,23.47 5.92,17.17 ; J3.4 26.53,9.22 26.53,9.81 24.57,11.77 10.52,11.77 9.17,13.12 9.17,14.12 8.62,14.67 6.62,14.67 5.92,15.37 5.92,17.17 ; 5.92,17.17 5.96,17.13 J15.3
  BOTTOM w0.3: v1(21.02,29.17) v1(21.02,33.17)
TL_URX/B5: length 42.7
  TOP w0.2: v1(39.77,42.32) 40.37,42.32 49.37,51.32 54.8,51.32 J33.3 J34.1 ; U1.19 22.77,42.58 23.29,43.1 25.32,43.1 25.75,42.67 29.88,42.67 30.23,42.32 v1(31.72,42.32)
  BOTTOM w0.2: v1(39.77,42.32) v1(31.72,42.32)
TL_UTX/B4: length 42.6
  TOP w0.2: v1(39.77,41.62) 40.37,41.62 49.12,50.37 53.33,50.37 J33.1 J34.3 ; v1(31.77,41.62) 30.28,41.62 29.63,42.27 25.58,42.27 25.15,42.7 23.55,42.7 23.27,42.42 U1.18
  BOTTOM w0.2: v1(39.77,41.62) v1(31.77,41.62)
TL_XC1: length 6.3
  TOP w0.2: U1.23 20.77,44.74 19.81,45.69 Y1.3 17.61,45.69 C13.2
TL_XC2: length 8.3
  TOP w0.2: C10.2 21.78,49 22.29,48.49 Y1.1 21.27,46.6 U1.22
URX: length 18.5
  TOP w0.2: J22.8 63.49,52.43 61.17,50.11 J34.2
  BOTTOM w0.2: J31.8 J22.8
UTX: length 21.6
  TOP w0.2: J33.2 57.7,50.11 58.97,51.37 59.12,51.37 61.27,51.37 61.92,52.02 61.92,59.88 J22.7
  BOTTOM w0.2: J31.7 J22.7
N19433324: length 5.6
  TOP w0.2: R25.1 41.6,36.02 41.59,36.02 R10.2 41.07,39.52 40.85,39.74 Q3.1
N19433336: length 13.3
  TOP w0.5: Q3.3 42.21,40.17 42.67,40.62 J8.2 45.52,39.37 48.57,36.32 D7.A
N19433338: length 13
  TOP w0.5: R11.1 56.54,40.47 56.39,40.62 J8.1 54.52,37.12 52.07,34.67 D7.C
N19452982: length 3.1
  TOP w0.3: U1.9 24.37,37.55 24.86,37.06 25.93,37.06 C6.2
N19453491: length 2.4
  TOP w0.5: J4.1 C33.1 L7.2
N19453517: length 22.8
  TOP w0.5: 0.55,53.89 0.55,41.46 L1.1 J4.2
N19478691: length 2.9
  TOP w0.2: J37.2 16.04,8.48 R42.1
N19478703: length 2.6
  TOP w0.2: R44.1 12.69,8.74 12.29,8.34 J37.3
N19478721: length 2.6
  TOP w0.2: R45.1 9.34,8.75 9.75,8.34 J37.4
N19478794: length 4.1
  TOP w0.2: R43.2 19.62,9.07 19.62,9.06 19.62,8.17 18.72,7.27 J37.1
N194550181: length 1.7
  TOP w0.2: R7.2 D4.A
N194550261: length 1.7
  TOP w0.2: R5.2 D2.A
N194550340: length 1.7
  TOP w0.2: R4.2 D1.A
N194550500: length 1.7
  TOP w0.2: R6.2 D3.A

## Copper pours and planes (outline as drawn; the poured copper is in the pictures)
GND on TOP: 3.05,5.3 1.1,6.1 0.3,8.05 0.3,35.47 9.27,35.47 9.27,68.04 64.39,68.04 65.74,66.69 65.74,50.26 68.28,47.72 68.28,15.2 65.74,12.66 65.74,6 65.53,5.51 65.04,5.3 ; 23 cut-outs
GND on BOTTOM: 3.05,5.3 1.1,6.1 0.3,8.05 0.3,35.47 9.27,35.47 9.27,68.04 64.39,68.04 65.74,66.69 65.74,50.26 68.28,47.72 68.28,15.2 65.74,12.66 65.74,6 65.53,5.51 65.04,5.3 ; 14 cut-outs

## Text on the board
Ref Des/Silkscreen Bottom: B6 | B7 | GND | SWS | 3V3 | 5V | NC | SCL/A3 | SDA/A4 | CK/C5 | DI | RST | DATE:2018-01-22 | DO | SN:C1T125A30_V1.1A | CN/C2 | C6 | C1 | A0 | A1 | CK | A5 | A2 | B3 | A6 | P5 | A7 | P3 | B0 | P1 | UTX | B1 | URX | P2 | B2 | TLSR8232DK32
User.Comments: RESET | [#=PWM] | GND | VIN | A0 | A1 | A2 | A3 | A4 | A5 | UNO_Rev3.01 | www.arduino.cc | IOREF | 3V3 | 5V | SCL | SDA | AREF | 13 | 12 | 11 | # | 10 | 9 | 8 | 7 | 6 | 5 | 4 | 3 | 2 | TX | 1 | 0 | RX | X1 | U1 | F1 | X2 | T1 | L1 | C12 | C9 | E2 | U3 | C2 | R3 | R1 | D1 | Y1 | U5' | R7 | C7 | E1 | C11 | U5 | C1 | R14 | R11 | U2 | R2 | IOH | Cp1 | C3 | C6 | R13 | R12 | R4 | RESET-EN | ZU4 | C8 | Y2 | C4 | R8 | C5 | C10 | IOL | R15 | D2 | R6 | ICSP | GROUND | ESD1 | R10 | R9 | ON | L | POWER | DIGITAL | ANALOG IN | Xduino
Ref Des/Silkscreen Top: RESET | GND | 3V3 | M_DO | S-DO | S_DI | M_DI | S_TX | M_TX | M_RX | S_RX
User.6: FIGURE | SIZE | 0.2 | 0.3 | 0.5 | 0.9 | 1.0 | DRILL CHART: TOP to BOTTOM | ALL UNITS ARE IN MILLIMETERS | PLATED | NON-PLATED | QTY | 358 | 142 | 2 | 92 | 12
